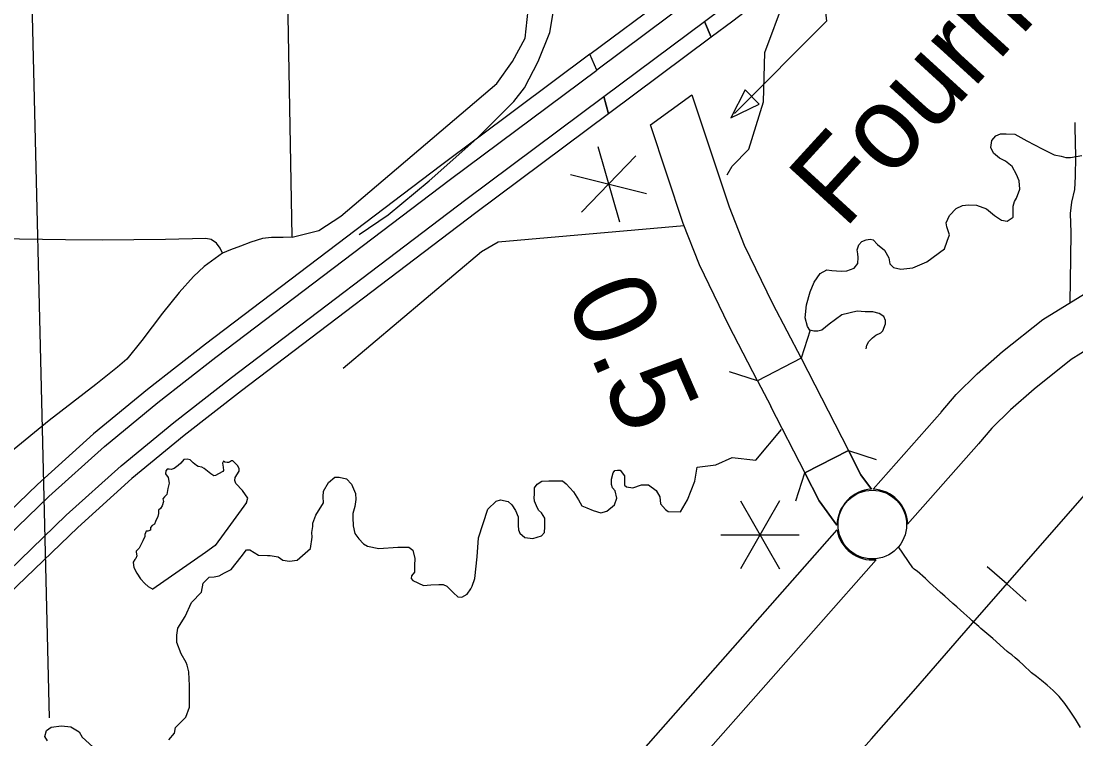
# Model space of a CAD drawing. Extents: x 1367863 to 1368197, y 380048 to 380261.
# Drawn here: x 1367970.56 to 1367991.45, y 380145.26 to 380159.47 of the extents above; entities that cross this region are included whole.
import ezdxf

# ---------------------------------------------------------------- set-up
doc = ezdxf.new("R2010")
doc.units = 0
for name, color, linetype in [('Level 10', 7, 'Continuous'), ('Level 15', 7, 'Continuous'), ('Level 21', 7, 'Continuous'), ('Level 24', 7, 'Continuous'), ('Level 31', 7, 'Continuous'), ('Level 32', 7, 'Continuous'), ('Level 33', 7, 'Continuous'), ('Level 34', 7, 'Continuous'), ('Level 35', 7, 'Continuous'), ('Level 37', 7, 'Continuous'), ('Level 40', 7, 'Continuous'), ('Level 48', 7, 'Continuous'), ('Level 5', 7, 'Continuous'), ('Level 6', 7, 'Continuous')]:
    doc.layers.add(name, color=color, linetype=linetype)

msp = doc.modelspace()

# ---------------------------------------------------------------- linework, layer by layer
at = {"layer": 'Level 10'}
msp.add_line((1367983.018, 380157.413), (1367983.843, 380158.008), dxfattribs=at)
for points in [[(1367988.776, 380151.732), (1367989.071, 380152.078), (1367989.492, 380152.486), (1367989.993, 380152.929), (1367990.793, 380153.566), (1367991.614, 380154.074), (1367992.598, 380154.665), (1367993.114, 380155.031), (1367993.202, 380155.12), (1367993.618, 380155.448), (1367993.715, 380155.544), (1367994.257, 380156.104), (1367997.013, 380159.313)], [(1367997.749, 380158.68), (1367994.975, 380155.45), (1367994.404, 380154.86), (1367994.26, 380154.719), (1367993.849, 380154.395), (1367993.743, 380154.288), (1367993.129, 380153.852), (1367992.119, 380153.246), (1367991.352, 380152.771), (1367990.618, 380152.186), (1367990.152, 380151.773), (1367989.78, 380151.413), (1367989.515, 380151.102)], [(1367983.843, 380158.008), (1367984.579, 380155.795), (1367984.878, 380155.037), (1367985.439, 380153.88), (1367986.003, 380152.795)], [(1367985.14, 380152.351), (1367984.572, 380153.444), (1367983.989, 380154.646), (1367983.667, 380155.463), (1367983.018, 380157.413)], [(1367986.003, 380152.795), (1367985.14, 380152.351)], [(1367986.003, 380152.795), (1367986.939, 380150.972)], [(1367985.14, 380152.351), (1367985.402, 380151.847)], [(1367985.4, 380151.85), (1367986.076, 380150.528)], [(1367987.428, 380150.204), (1367988.795, 380151.752)], [(1367989.522, 380151.11), (1367988.113, 380149.515)], [(1367986.076, 380150.528), (1367986.939, 380150.972)], [(1367986.939, 380150.972), (1367986.076, 380150.528)], [(1367986.939, 380150.972), (1367987.186, 380150.49), (1367987.395, 380150.205)], [(1367987.395, 380150.205), (1367987.186, 380150.49), (1367986.939, 380150.972)], [(1367986.714, 380149.493), (1367986.358, 380149.978), (1367986.076, 380150.528)], [(1367986.076, 380150.528), (1367986.358, 380149.978), (1367986.714, 380149.493)], [(1367979.459, 380141.243), (1367979.499, 380141.278), (1367979.93, 380141.711), (1367986.716, 380149.398)], [(1367987.489, 380148.808), (1367980.638, 380141.048), (1367980.164, 380140.57)]]:
    msp.add_lwpolyline(points, dxfattribs=at)
for centre, radius, start, end in [((1367987.443, 380149.478), 0.729, 93.7974, 178.7856), ((1367987.443, 380149.478), 0.729, 93.7974, 178.7856), ((1367987.407, 380149.498), 0.707, 1.3764, 88.2821), ((1367987.417, 380149.514), 0.71, 189.4286, 275.8682)]:
    msp.add_arc(centre, radius, start, end, dxfattribs=at)
at = {"layer": 'Level 15'}
for p, q in [((1367981.823, 380158.812), (1367983.775, 380160.267)), ((1367983.888, 380159.94), (1367981.956, 380158.5)), ((1367982.096, 380157.975), (1367984.089, 380159.461)), ((1367984.225, 380159.15), (1367982.189, 380157.633))]:
    msp.add_line(p, q, dxfattribs=at)
for points in [[(1367984.089, 380159.461), (1367984.455, 380159.734), (1367986.671, 380161.43), (1367990.068, 380163.952), (1367994.62, 380167.377), (1367995.971, 380168.419), (1367996.483, 380168.878), (1367996.881, 380169.237), (1367998.451, 380170.888), (1367998.864, 380171.423), (1367999.916, 380172.924), (1368002.563, 380177.46)], [(1368002.944, 380177.46), (1368002.871, 380177.333), (1368000.194, 380172.746), (1367999.13, 380171.227), (1367998.702, 380170.673), (1367997.112, 380169.001), (1367996.703, 380168.633), (1367996.182, 380168.165), (1367994.82, 380167.114), (1367990.266, 380163.688), (1367986.87, 380161.166), (1367984.654, 380159.47), (1367984.225, 380159.15)], [(1367984.089, 380159.461), (1367984.225, 380159.15)], [(1367984.225, 380159.15), (1367984.089, 380159.461)], [(1367981.823, 380158.812), (1367978.861, 380156.604), (1367974.211, 380153.076), (1367973.061, 380152.177), (1367971.993, 380151.299), (1367970.884, 380150.3), (1367968.811, 380148.303)], [(1367981.956, 380158.5), (1367981.823, 380158.812)], [(1367981.956, 380158.5), (1367981.823, 380158.812)], [(1367969.039, 380148.066), (1367971.109, 380150.058), (1367972.208, 380151.049), (1367973.268, 380151.92), (1367974.413, 380152.815), (1367979.059, 380156.34), (1367981.956, 380158.5)], [(1367969.389, 380147.702), (1367971.453, 380149.689), (1367972.537, 380150.666), (1367973.583, 380151.526), (1367974.721, 380152.415), (1367979.362, 380155.937), (1367982.096, 380157.975)], [(1367982.096, 380157.975), (1367982.189, 380157.633)], [(1367982.189, 380157.633), (1367982.096, 380157.975)], [(1367982.189, 380157.633), (1367979.561, 380155.673), (1367974.922, 380152.154), (1367973.79, 380151.269), (1367972.752, 380150.416), (1367971.678, 380149.448), (1367969.618, 380147.465)]]:
    msp.add_lwpolyline(points, dxfattribs=at)
at = {"layer": 'Level 21'}
msp.add_lwpolyline([(1367985.353, 380170.106), (1367986.507, 380159.464), (1367984.684, 380157.641)], dxfattribs=at)
msp.add_lwpolyline([(1367985.176, 380157.827), (1367984.899, 380158.109), (1367984.614, 380157.551)], close=True, dxfattribs=at)
at = {"layer": 'Level 24'}
msp.add_circle((1367987.414, 380149.505), 0.679, dxfattribs=at)
at = {"layer": 'Level 31'}
for points in [[(1367974.548, 380154.873), (1367974.498, 380154.973), (1367974.427, 380155.073), (1367974.32, 380155.144), (1367974.214, 380155.164), (1367973.414, 380155.148), (1367972.16, 380155.132), (1367971.438, 380155.137), (1367970.529, 380155.154), (1367969.713, 380155.17)], [(1367975.923, 380155.194), (1367975.747, 380155.187), (1367975.519, 380155.184), (1367975.337, 380155.165), (1367975.109, 380155.094), (1367974.903, 380155.016), (1367974.704, 380154.945), (1367974.548, 380154.873)], [(1367974.548, 380154.873), (1367974.185, 380154.61), (1367973.972, 380154.411), (1367973.688, 380154.098), (1367973.361, 380153.686), (1367972.948, 380153.145), (1367972.65, 380152.776), (1367972.465, 380152.619), (1367972.038, 380152.278), (1367971.114, 380151.567), (1367970.347, 380150.941), (1367969.465, 380150.215), (1367968.768, 380149.675), (1367968.257, 380149.277), (1367967.83, 380148.964), (1367967.304, 380148.494), (1367966.949, 380148.153), (1367966.024, 380147.243), (1367965.157, 380146.389), (1367964.077, 380145.337), (1367963.508, 380144.774)]]:
    msp.add_lwpolyline(points, dxfattribs=at)
at = {"layer": 'Level 32'}
msp.add_lwpolyline([(1367983.685, 380155.416), (1367980.003, 380155.094), (1367979.672, 380154.905), (1367976.936, 380152.593)], dxfattribs=at)
at = {"layer": 'Level 33'}
for points in [[(1367975.923, 380155.194), (1367976.455, 380155.327), (1367976.888, 380155.605), (1367979.98, 380158.235), (1367980.29, 380158.668), (1367980.537, 380159.132), (1367980.599, 380159.688), (1367980.599, 380160.121), (1367980.568, 380161.142), (1367980.63, 380161.452), (1367980.877, 380161.792), (1367981.279, 380162.132), (1367981.836, 380162.41)], [(1367991.334, 380153.901), (1367991.343, 380154.78), (1367991.35, 380155.287)], [(1367988.464, 380148.436), (1367988.299, 380148.581), (1367988.268, 380148.603), (1367988.245, 380148.621), (1367988.213, 380148.651), (1367987.929, 380149.062)], [(1367991.537, 380145.49), (1367991.435, 380145.654), (1367991.331, 380145.812), (1367991.224, 380145.961), (1367991.114, 380146.101), (1367990.996, 380146.223), (1367990.878, 380146.327), (1367990.767, 380146.418), (1367990.663, 380146.501), (1367990.569, 380146.571), (1367990.401, 380146.73), (1367990.32, 380146.801), (1367990.244, 380146.869), (1367990.174, 380146.927), (1367990.119, 380146.968), (1367990.086, 380146.996), (1367989.8, 380147.25), (1367989.762, 380147.283), (1367989.722, 380147.316), (1367989.681, 380147.35), (1367989.641, 380147.383), (1367989.602, 380147.417), (1367989.563, 380147.451), (1367989.522, 380147.486), (1367989.482, 380147.52), (1367989.439, 380147.559), (1367989.393, 380147.599), (1367989.342, 380147.645), (1367989.286, 380147.697), (1367989.224, 380147.752), (1367989.157, 380147.813), (1367989.085, 380147.876), (1367989.009, 380147.945), (1367988.929, 380148.014), (1367988.847, 380148.087), (1367988.766, 380148.161), (1367988.685, 380148.234), (1367988.61, 380148.298), (1367988.549, 380148.359), (1367988.499, 380148.404), (1367988.464, 380148.436)]]:
    msp.add_lwpolyline(points, dxfattribs=at)
at = {"layer": 'Level 34'}
msp.add_lwpolyline([(1367991.35, 380155.287), (1367991.335, 380155.662), (1367991.364, 380155.884), (1367991.421, 380156.135), (1367991.436, 380156.393), (1367991.443, 380156.786), (1367991.428, 380157.366), (1367991.428, 380157.459)], dxfattribs=at)
at = {"layer": 'Level 35'}
for points in [[(1367986.613, 380154.53), (1367986.794, 380154.517), (1367986.91, 380154.524), (1367987.052, 380154.582), (1367987.129, 380154.672), (1367987.136, 380154.788), (1367987.129, 380154.866), (1367987.116, 380154.943), (1367987.149, 380155.04), (1367987.207, 380155.105), (1367987.29, 380155.143), (1367987.368, 380155.156), (1367987.432, 380155.137), (1367987.516, 380155.046), (1367987.652, 380154.937), (1367987.742, 380154.782), (1367987.761, 380154.666), (1367987.832, 380154.595), (1367987.981, 380154.562), (1367988.213, 380154.588), (1367988.49, 380154.704), (1367988.845, 380154.963), (1367988.897, 380155.111), (1367988.942, 380155.24), (1367988.89, 380155.395), (1367988.877, 380155.479), (1367988.942, 380155.621), (1367989.077, 380155.763), (1367989.2, 380155.821), (1367989.316, 380155.834), (1367989.477, 380155.827), (1367989.677, 380155.75), (1367989.832, 380155.621), (1367989.974, 380155.53), (1367990.084, 380155.511), (1367990.122, 380155.537), (1367990.206, 380155.589), (1367990.206, 380155.692), (1367990.206, 380155.808), (1367990.226, 380155.898), (1367990.271, 380155.963), (1367990.335, 380156.144), (1367990.322, 380156.305), (1367990.271, 380156.434), (1367990.181, 380156.589), (1367990.051, 380156.699), (1367989.935, 380156.757), (1367989.813, 380156.853), (1367989.761, 380156.97), (1367989.781, 380157.103), (1367989.858, 380157.199), (1367989.955, 380157.238), (1367990.064, 380157.238), (1367990.239, 380157.232), (1367990.471, 380157.096), (1367990.774, 380156.941), (1367991.013, 380156.819), (1367991.155, 380156.793), (1367991.245, 380156.767), (1367991.335, 380156.767), (1367991.561, 380156.806)], [(1367987.291, 380152.984), (1367987.303, 380153.056), (1367987.348, 380153.127), (1367987.419, 380153.198), (1367987.484, 380153.256), (1367987.581, 380153.301), (1367987.619, 380153.339), (1367987.677, 380153.475), (1367987.677, 380153.546), (1367987.639, 380153.623), (1367987.548, 380153.682), (1367987.426, 380153.714), (1367987.271, 380153.714), (1367987.116, 380153.727), (1367986.813, 380153.656), (1367986.561, 380153.469), (1367986.413, 380153.352), (1367986.336, 380153.333), (1367986.258, 380153.333), (1367986.174, 380153.352), (1367986.129, 380153.423), (1367986.084, 380153.598), (1367986.11, 380153.856), (1367986.181, 380154.114), (1367986.265, 380154.304), (1367986.381, 380154.472), (1367986.516, 380154.543), (1367986.613, 380154.53)], [(1367982.981, 380150.293), (1367983.136, 380150.177), (1367983.207, 380150.055), (1367983.22, 380149.913), (1367983.317, 380149.803), (1367983.374, 380149.765), (1367983.618, 380149.76), (1367983.757, 380149.992), (1367983.897, 380150.364), (1367983.943, 380150.643), (1367984.315, 380150.689), (1367984.641, 380150.829), (1367985.105, 380150.782), (1367985.617, 380151.387)], [(1367975.023, 380149.94), (1367975.048, 380150.027), (1367974.941, 380150.18), (1367974.808, 380150.318), (1367974.793, 380150.374), (1367974.798, 380150.436), (1367974.875, 380150.563), (1367974.875, 380150.609), (1367974.849, 380150.665), (1367974.793, 380150.727), (1367974.752, 380150.768), (1367974.727, 380150.768), (1367974.686, 380150.742), (1367974.665, 380150.732), (1367974.635, 380150.732), (1367974.594, 380150.742), (1367974.563, 380150.763), (1367974.543, 380150.717), (1367974.558, 380150.64), (1367974.563, 380150.574), (1367974.553, 380150.553), (1367974.466, 380150.512), (1367974.41, 380150.476), (1367974.374, 380150.471), (1367974.313, 380150.507), (1367974.18, 380150.614), (1367974.139, 380150.64), (1367974.063, 380150.655), (1367974.032, 380150.676), (1367973.966, 380150.727), (1367973.904, 380150.788), (1367973.848, 380150.798), (1367973.777, 380150.793), (1367973.721, 380150.722), (1367973.669, 380150.676), (1367973.588, 380150.614), (1367973.532, 380150.594), (1367973.491, 380150.604), (1367973.45, 380150.604), (1367973.424, 380150.568), (1367973.419, 380150.507), (1367973.47, 380150.436), (1367973.491, 380150.323), (1367973.465, 380150.221), (1367973.445, 380150.098), (1367973.399, 380150.052), (1367973.363, 380150.017), (1367973.378, 380149.96), (1367973.353, 380149.879), (1367973.317, 380149.823), (1367973.276, 380149.787), (1367973.276, 380149.725), (1367973.266, 380149.664), (1367973.22, 380149.567), (1367973.2, 380149.511), (1367973.154, 380149.485), (1367973.118, 380149.45), (1367973.118, 380149.393), (1367973.067, 380149.373), (1367973.036, 380149.373), (1367973.011, 380149.307), (1367973.011, 380149.266), (1367972.97, 380149.184), (1367972.929, 380149.102), (1367972.893, 380149.041), (1367972.837, 380148.98), (1367972.837, 380148.964), (1367972.842, 380148.918), (1367972.847, 380148.888), (1367972.832, 380148.836), (1367972.812, 380148.816), (1367972.776, 380148.76), (1367972.776, 380148.755), (1367972.791, 380148.653), (1367972.847, 380148.545), (1367972.924, 380148.433), (1367973.011, 380148.336), (1367973.072, 380148.28), (1367973.164, 380148.229)], [(1367976.317, 380149.351), (1367976.336, 380149.467), (1367976.336, 380149.532), (1367976.395, 380149.693), (1367976.543, 380149.938), (1367976.536, 380150.055), (1367976.549, 380150.164), (1367976.646, 380150.339), (1367976.769, 380150.442), (1367976.853, 380150.442), (1367977.001, 380150.41), (1367977.098, 380150.306), (1367977.182, 380150.119), (1367977.188, 380150.003), (1367977.169, 380149.861), (1367977.13, 380149.725), (1367977.124, 380149.648), (1367977.136, 380149.48), (1367977.169, 380149.325), (1367977.246, 380149.222), (1367977.336, 380149.125), (1367977.42, 380149.08), (1367977.64, 380149.029), (1367978.02, 380149.061), (1367978.233, 380149.061), (1367978.317, 380148.996), (1367978.356, 380148.835), (1367978.349, 380148.693), (1367978.349, 380148.564), (1367978.291, 380148.493), (1367978.285, 380148.435), (1367978.317, 380148.396), (1367978.523, 380148.299), (1367978.672, 380148.312), (1367978.827, 380148.319), (1367978.917, 380148.319), (1367978.988, 380148.286), (1367979.123, 380148.151), (1367979.207, 380148.073), (1367979.285, 380148.067), (1367979.394, 380148.131), (1367979.465, 380148.235), (1367979.491, 380148.286), (1367979.543, 380148.441), (1367979.588, 380148.867), (1367979.614, 380149.241), (1367979.801, 380149.809), (1367979.968, 380149.971), (1367980.052, 380149.997), (1367980.201, 380149.964), (1367980.278, 380149.893), (1367980.349, 380149.784), (1367980.401, 380149.661), (1367980.401, 380149.487), (1367980.407, 380149.403), (1367980.433, 380149.332), (1367980.536, 380149.248), (1367980.691, 380149.229), (1367980.865, 380149.28), (1367980.923, 380149.345), (1367980.93, 380149.461), (1367980.93, 380149.571), (1367980.93, 380149.635), (1367980.865, 380149.738), (1367980.801, 380149.79), (1367980.762, 380149.874), (1367980.723, 380149.971), (1367980.717, 380150.042), (1367980.723, 380150.1), (1367980.723, 380150.229), (1367980.775, 380150.306), (1367980.872, 380150.364), (1367981.007, 380150.371), (1367981.072, 380150.371), (1367981.149, 380150.371), (1367981.278, 380150.371), (1367981.349, 380150.313), (1367981.497, 380150.151), (1367981.594, 380149.997), (1367981.659, 380149.874), (1367981.762, 380149.835), (1367981.884, 380149.784), (1367982.039, 380149.738), (1367982.155, 380149.771), (1367982.31, 380149.893), (1367982.355, 380150.029), (1367982.323, 380150.171), (1367982.271, 380150.235), (1367982.246, 380150.3), (1367982.246, 380150.403), (1367982.284, 380150.526), (1367982.317, 380150.577), (1367982.368, 380150.584), (1367982.42, 380150.584), (1367982.504, 380150.468), (1367982.504, 380150.364), (1367982.504, 380150.287), (1367982.549, 380150.255), (1367982.671, 380150.235), (1367982.846, 380150.293), (1367982.981, 380150.293)], [(1367975.023, 380149.94), (1367974.706, 380149.506), (1367974.4, 380149.092), (1367974.211, 380148.954), (1367973.164, 380148.229)], [(1367973.485, 380145.243), (1367973.595, 380145.379), (1367973.614, 380145.489), (1367973.821, 380145.695), (1367973.892, 380145.889), (1367973.892, 380146.044), (1367973.892, 380146.179), (1367973.892, 380146.328), (1367973.885, 380146.444), (1367973.879, 380146.592), (1367973.846, 380146.721), (1367973.827, 380146.773), (1367973.73, 380146.944), (1367973.64, 380147.17), (1367973.64, 380147.318), (1367973.659, 380147.454), (1367973.808, 380147.686), (1367973.93, 380147.964), (1367974.13, 380148.17), (1367974.162, 380148.344), (1367974.285, 380148.467), (1367974.382, 380148.474), (1367974.479, 380148.493), (1367974.588, 380148.551), (1367974.717, 380148.615), (1367974.917, 380148.867), (1367975.02, 380149.003), (1367975.085, 380149.003), (1367975.259, 380148.899), (1367975.44, 380148.893), (1367975.491, 380148.893), (1367975.646, 380148.867), (1367975.743, 380148.803), (1367975.872, 380148.783), (1367976.027, 380148.803), (1367976.291, 380149.029), (1367976.324, 380149.254), (1367976.317, 380149.351)], [(1367971.079, 380145.224), (1367971.027, 380145.308), (1367971.06, 380145.431), (1367971.15, 380145.495), (1367971.356, 380145.521), (1367971.543, 380145.502), (1367971.705, 380145.405), (1367971.769, 380145.295), (1367972.124, 380144.972)]]:
    msp.add_lwpolyline(points, dxfattribs=at)
at = {"layer": 'Level 37'}
for points in [[(1367986.18, 380153.35), (1367986.003, 380152.795)], [(1367985.14, 380152.351), (1367984.586, 380152.528)], [(1367986.939, 380150.971), (1367987.493, 380150.793)], [(1367985.898, 380149.974), (1367986.076, 380150.528)]]:
    msp.add_lwpolyline(points, dxfattribs=at)
at = {"layer": 'Level 40'}
for q in [(1367989.69, 380148.667), (1367990.461, 380147.991)]:
    msp.add_line((1367990.075, 380148.329), q, dxfattribs=at)
for points in [[(1367989.355, 380147.507), (1367991.846, 380150.349), (1367993.31, 380152.01), (1367995.255, 380154.24), (1367997.659, 380156.983), (1367999.101, 380158.645), (1368000.784, 380160.612), (1368001.166, 380161.093), (1368001.865, 380162.022), (1368002.903, 380163.465), (1368003.701, 380164.536), (1368005.384, 380166.853), (1368006.389, 380168.208), (1368007.897, 380170.285), (1368009.536, 380172.515), (1368010.803, 380174.253), (1368012.366, 380176.384), (1368013.156, 380177.46)], [(1367975.603, 380131.816), (1367976.298, 380132.599), (1367979.095, 380135.801), (1367980.876, 380137.834), (1367981.652, 380138.708), (1367982.351, 380139.484), (1367983.389, 380140.687), (1367984.591, 380142.064), (1367986.088, 380143.791), (1367987.399, 380145.266), (1367988.273, 380146.261), (1367989.355, 380147.507), (1367991.846, 380150.349)], [(1367975.172, 380131.331), (1367976.298, 380132.599), (1367979.095, 380135.801), (1367980.876, 380137.834), (1367981.652, 380138.708), (1367982.351, 380139.484), (1367983.389, 380140.687), (1367984.591, 380142.064), (1367986.088, 380143.791), (1367987.399, 380145.266), (1367988.273, 380146.261), (1367989.355, 380147.507)]]:
    msp.add_lwpolyline(points, dxfattribs=at)
at = {"layer": 'Level 48'}
for p, q in [((1367981.977, 380156.99), (1367982.405, 380155.498)), ((1367982.73, 380156.802), (1367981.652, 380155.686)), ((1367981.438, 380156.432), (1367982.944, 380156.056)), ((1367985.577, 380149.975), (1367984.801, 380148.631)), ((1367984.801, 380149.975), (1367985.577, 380148.631)), ((1367984.412, 380149.303), (1367985.965, 380149.303))]:
    msp.add_line(p, q, dxfattribs=at)
at = {"layer": 'Level 5'}
msp.add_lwpolyline([(1367970.655, 380164.472), (1367971.116, 380145.679)], dxfattribs=at)
at = {"layer": 'Level 6'}
for points in [[(1367975.923, 380155.206), (1367975.756, 380164.667)], [(1367977.254, 380155.244), (1367977.828, 380155.633), (1367978.636, 380156.306), (1367979.58, 380157.144), (1367980.318, 380157.876), (1367980.524, 380158.147), (1367980.796, 380158.667), (1367981.026, 380159.245), (1367981.091, 380159.629), (1367981.12, 380159.977), (1367981.161, 380160.302), (1367981.226, 380160.508), (1367981.285, 380160.656), (1367981.386, 380160.85), (1367981.663, 380161.157), (1367981.881, 380161.334), (1367982.035, 380161.63), (1367982.389, 380161.795), (1367982.571, 380161.857)], [(1367984.537, 380156.429), (1367984.639, 380156.599), (1367984.97, 380156.931), (1367985.26, 380157.869), (1367985.287, 380158.848), (1367985.674, 380159.897), (1367985.809, 380160.1)]]:
    msp.add_lwpolyline(points, dxfattribs=at)

# ---------------------------------------------------------------- texts
at = {"layer": 'Level 35'}
msp.add_text('Fourmile', height=1.6394, rotation=47.5543, dxfattribs=at).set_placement((1367986.857, 380155.33))
at = {"layer": 'Level 48'}
msp.add_text('0.5', height=1.6394, rotation=293.5128, dxfattribs=at).set_placement((1367981.327, 380153.997))

doc.saveas('drawing.dxf')
